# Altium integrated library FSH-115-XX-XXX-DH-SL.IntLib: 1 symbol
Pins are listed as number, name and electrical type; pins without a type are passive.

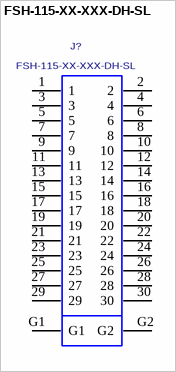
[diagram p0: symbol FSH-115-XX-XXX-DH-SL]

## FSH-115-XX-XXX-DH-SL
designator J?
SHROUDED HEADER, .050" (1.27mm) PITCH, 50 PINS WITH SOLDER LOCKS.; MANUFACTURER: SAMTEC
footprint FSH-115-XX-XXX-DH-SL
pins: 1, 2, 3, 4, 5, 6, 7, 8, 9, 10, 11, 12, 13, 14, 15, 16, 17, 18, 19, 20, 21, 22, 23, 24, 25, 26, 27, 28, 29, 30, G1, G2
